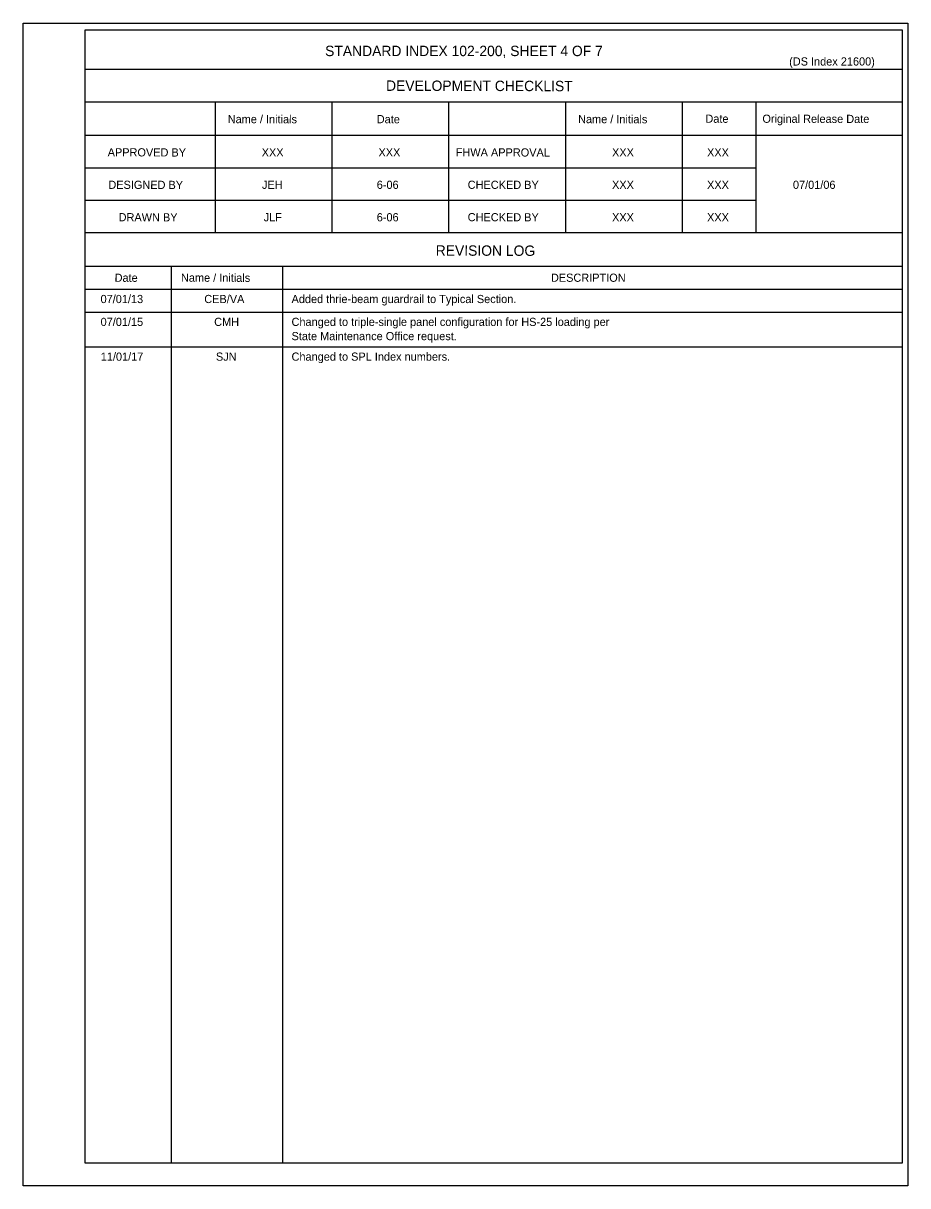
# Model space of a CAD drawing. Extents: x 11137.4 to 11208.2, y 76297.7 to 76332.4.
# Drawn here: x 11186.43 to 11208.24, y 76303.69 to 76332.36 of the extents above; entities that cross this region are included whole.
import ezdxf

# ---------------------------------------------------------------- set-up
doc = ezdxf.new("R2010")
doc.units = 0
for name, color, linetype in [('Border', 7, 'Continuous'), ('PlotBorder_dp', 7, 'Continuous'), ('TextStructures', 7, 'Continuous')]:
    doc.layers.add(name, color=color, linetype=linetype)

msp = doc.modelspace()

# ---------------------------------------------------------------- linework, layer by layer
at = {"layer": 'Border'}
for p, q in [((11208.105, 76331.214), (11187.958, 76331.214)), ((11208.105, 76330.414), (11187.958, 76330.414)), ((11191.158, 76330.414), (11191.158, 76327.186)), ((11194.038, 76330.414), (11194.038, 76327.186)), ((11196.918, 76330.414), (11196.918, 76327.186)), ((11199.798, 76330.414), (11199.798, 76327.186)), ((11202.678, 76330.414), (11202.678, 76327.186)), ((11204.493, 76330.414), (11204.493, 76327.186)), ((11208.105, 76329.586), (11187.958, 76329.586)), ((11204.493, 76328.786), (11187.958, 76328.786)), ((11204.493, 76327.986), (11187.958, 76327.986)), ((11208.105, 76327.186), (11187.958, 76327.186)), ((11208.105, 76326.358), (11187.958, 76326.358)), ((11190.078, 76326.358), (11190.078, 76304.251)), ((11192.82, 76326.358), (11192.82, 76304.251)), ((11208.105, 76325.794), (11187.958, 76325.794))]:
    msp.add_line(p, q, dxfattribs=at)
msp.add_lwpolyline([(11187.958, 76332.194), (11208.105, 76332.194), (11208.105, 76304.251), (11187.958, 76304.251)], close=True, dxfattribs=at)
at = {"layer": 'PlotBorder_dp'}
msp.add_line((11186.427, 76303.69), (11186.427, 76303.69), dxfattribs=at)
msp.add_lwpolyline([(11186.427, 76332.357), (11208.241, 76332.357), (11208.241, 76303.69), (11186.427, 76303.69)], close=True, dxfattribs=at)
at = {"layer": 'TextStructures'}
for p, q in [((11187.958, 76325.23), (11208.105, 76325.23)), ((11187.958, 76324.374), (11208.105, 76324.374))]:
    msp.add_line(p, q, dxfattribs=at)

# ---------------------------------------------------------------- texts
for s, height, p in [('STANDARD INDEX 102-200, SHEET 4 OF 7', 0.256, (11193.871, 76331.546)), ('(DS Index 21600)', 0.2016, (11205.316, 76331.314)), ('XXX', 0.2016, (11192.308, 76329.072)), ('XXX', 0.2016, (11195.188, 76329.072)), ('XXX', 0.2016, (11200.948, 76329.072)), ('XXX', 0.2016, (11203.291, 76329.072)), ('JEH', 0.2016, (11192.315, 76328.272)), ('6-06', 0.2016, (11195.145, 76328.272)), ('XXX', 0.2016, (11200.948, 76328.272)), ('XXX', 0.2016, (11203.291, 76328.272)), ('07/01/06', 0.2016, (11205.409, 76328.272)), ('JLF', 0.2016, (11192.357, 76327.472)), ('6-06', 0.2016, (11195.145, 76327.472)), ('XXX', 0.2016, (11200.948, 76327.472)), ('XXX', 0.2016, (11203.291, 76327.472)), ('DESCRIPTION', 0.2016, (11199.441, 76325.981)), ('07/01/13', 0.2016, (11188.334, 76325.456)), ('CEB/VA', 0.2016, (11190.892, 76325.456)), ('Added thrie-beam guardrail to Typical Section.', 0.2016, (11193.044, 76325.456)), ('07/01/15', 0.2016, (11188.335, 76324.892)), ('CMH', 0.2016, (11191.136, 76324.892)), ('Changed to triple-single panel configuration for HS-25 loading per ', 0.2016, (11193.044, 76324.892)), ('State Maintenance Office request.', 0.2016, (11193.044, 76324.541)), ('11/01/17', 0.2016, (11188.339, 76324.035)), ('SJN', 0.2016, (11191.179, 76324.035)), ('Changed to SPL Index numbers.', 0.2016, (11193.044, 76324.035))]:
    msp.add_text(s, height=height, dxfattribs=at).set_placement(p)
for s, height, p in [('DEVELOPMENT CHECKLIST', 0.256, (11195.374, 76330.69)), ('Name / Initials', 0.2016, (11191.47, 76329.893)), ('Date', 0.2016, (11195.145, 76329.891)), ('Name / Initials', 0.2016, (11200.11, 76329.893)), ('Date', 0.2016, (11203.25, 76329.903)), ('Original Release Date', 0.2016, (11204.656, 76329.902)), ('APPROVED BY', 0.2016, (11188.509, 76329.074)), ('FHWA APPROVAL', 0.2016, (11197.093, 76329.074)), ('DESIGNED BY', 0.2016, (11188.526, 76328.273)), ('CHECKED BY', 0.2016, (11197.388, 76328.274)), ('DRAWN BY', 0.2016, (11188.779, 76327.473)), ('CHECKED BY', 0.2016, (11197.388, 76327.474)), ('REVISION LOG', 0.256, (11196.599, 76326.625)), ('Date', 0.2016, (11188.68, 76325.981)), ('Name / Initials', 0.2016, (11190.317, 76325.983))]:
    msp.add_text(s, height=height, rotation=359.8756, dxfattribs=at).set_placement(p)

doc.saveas('drawing.dxf')
